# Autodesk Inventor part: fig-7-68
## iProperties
Shininess: 64.0
Length Units: 11269
Angle Units: 11279
Time Units: 11290
Mass Units: 11283
Length Display Precision: 3
Angle Display Precision: 2
Compacted: True
Part Number: fig-7-68
Document SubType Name: Modeling
Created: 2002-12
Designer: deepak
Density: 1 g/cm^3
Density: 0.0
Volumn: 0.0
Area: 0.0
PropertySet Name: Model Information
Control State: 0
Master: False
Checked Out: False
Author: deepak
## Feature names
1. Extrusion1
